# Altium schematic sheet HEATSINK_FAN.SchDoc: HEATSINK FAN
size A3; Author: Silvio Navaretti; CompanyName: ARDUINO; DrawnBy: Silvio Navaretti; Engineer: Silvio Navaretti; Organization: ARDUINO; SheetNumber: 50; SheetTotal: 51; RevAuthor: Silvio Navaretti
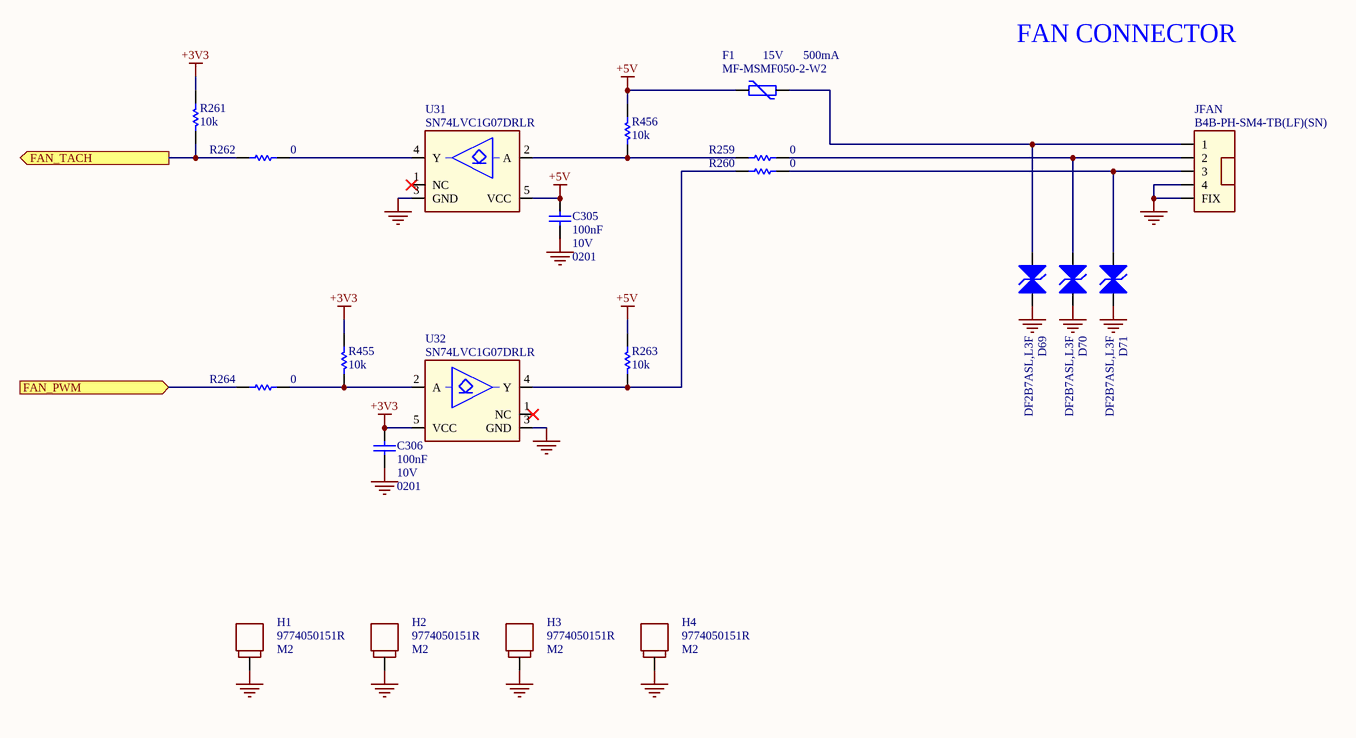
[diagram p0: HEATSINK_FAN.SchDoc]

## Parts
C305  value 100nF  Voltage: 10V  Case Code (Imperial): 0201  [CAP-0201]  (hidden comment: CL03A104KP3NNNC)
C306  value 100nF  Voltage: 10V  Case Code (Imperial): 0201  [CAP-0201]  (hidden comment: CL03A104KP3NNNC)
D69  DF2B7ASL,L3F  [DF2B7ASL,L3F]
D70  DF2B7ASL,L3F  [DF2B7ASL,L3F]
D71  DF2B7ASL,L3F  [DF2B7ASL,L3F]
F1  MF-MSMF050-2-W2  Hold Current: 500mA  Operating Supply Voltage: 15V  [1812]
H1  9774050151R  [9774050151R]
H2  9774050151R  [9774050151R]
H3  9774050151R  [9774050151R]
H4  9774050151R  [9774050151R]
JFAN  B4B-PH-SM4-TB(LF)(SN)  [B4B-PH-SM4-TB(LF)(SN)]
R259  value 0  [RES-0201]  (hidden comment: CRCW02010000Z0ED)
R260  value 0  [RES-0201]  (hidden comment: CRCW02010000Z0ED)
R261  value 10k  [RES-0201]  (hidden comment: RC0201FR-0710KL)
R262  value 0  [RES-0201]  (hidden comment: CRCW02010000Z0ED)
R263  value 10k  [RES-0201]  (hidden comment: RC0201FR-0710KL)
R264  value 0  [RES-0201]  (hidden comment: CRCW02010000Z0ED)
R455  value 10k  [RES-0201]  (hidden comment: RC0201FR-0710KL)
R456  value 10k  [RES-0201]  (hidden comment: RC0201FR-0710KL)
U31  SN74LVC1G07DRLR  [TI DRL DRL0005A]
U32  SN74LVC1G07DRLR  [TI DRL DRL0005A]

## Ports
FAN_PWM (in), FAN_TACH (out)

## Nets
+3V3: C306.2 R261.2 R455.2 U32.5(VCC)
+5V: C305.2 F1.1 R263.2 R456.2 U31.5(VCC)
GND: C305.1 C306.1 D69.1(A1) D70.1(A1) D71.1(A1) H1.1 H2.1 H3.1 H4.1 JFAN.4 JFAN.FIX U31.3(GND) U32.3(GND)
FAN_PWM: R264.2 ; port FAN_PWM
FAN_TACH: R261.1 R262.2 ; port FAN_TACH
NetD69_2: D69.2(A2) F1.2 JFAN.1
NetD70_2: D70.2(A2) JFAN.2 R259.1
NetD71_2: D71.2(A2) JFAN.3 R260.1
NetR259_2: R259.2 R456.1 U31.2(A)
NetR260_2: R260.2 R263.1 U32.4(Y)
NetR262_1: R262.1 U31.4(Y)
NetR264_1: R264.1 R455.1 U32.2(A)

Not connected (* = marked no-connect by the designer): U31 1(NC)*; U32 1(NC)*

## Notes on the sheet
- FAN CONNECTOR

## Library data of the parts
C305 C306 = C0113-A.6: CAP CHIP 0201 100nF 10% 10V X5R; Manufacturer: Samsung Electro-Mechanics; Code Arduino: C0113
D69-D71 = D0099-5: TVS BIDIRECTIONAL SMD Vr 5.5V, Vbr min 5.8V, 0.62x0.32mm; Manufacturer: TOSHIBA; Vforward max: 0V; Ireverse max: 1µA; Power max: 80W; Code Arduino: D0099; Vreverse max: 20V
F1 = P0002-A.7: PTC RESET FUSE 15V 500MA 1812 LOGO OO ARDUINO; Manufacturer: Bourns; Approvals: UL,CSA,TUV; Time to Trip: 0.15s; Max Current Rating: 100A; Trip Current: 1A; Resistance: 150mR; Code Arduino: 3335; Power Dissipation: 800mW
H1-H4 = S0005-A.6: M2.5 SPACER SMT ROUND STEEL H=5mm; Manufacturer: Würth Elektronik; Code Arduino: S0005
JFAN = J0557-A.2: CONN Header SMD 1x4 vertical polarized; Manufacturer: JST; Code Arduino: J0557
R259 R260 R262 R264 = R0140-A.21: RES CHIP 0201 0R; Manufacturer: Vishay; Temperature coefficient: 0ppm; Code Arduino: R0140; Power: 50mW; Tolerance: 0%
R261 R263 R455 R456 = R0145-A.21: RES CHIP 0201 10k 1% 1/20W; Manufacturer: Yageo; Power: 50mW; Temperature coefficient: 200ppm; Code Arduino: R0145
U31 U32 = U0494-A.2: IC buffer open drain, 1.65V to 5.5V, 32mA sink current, SOT-5X3 1.6mmx1.6mm; Manufacturer: Texas Instruments; Code Arduino: U0494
